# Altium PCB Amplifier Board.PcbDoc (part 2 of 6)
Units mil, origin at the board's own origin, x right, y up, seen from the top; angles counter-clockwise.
Board outline 6000 x 2640 mil, 6 copper layers (Top Layer, GND, VCC, BASES, GND (Plane3), Bottom Layer), stack 63.9 mil thick; 884 components, 484 nets, 2029 pads, 464 vias.
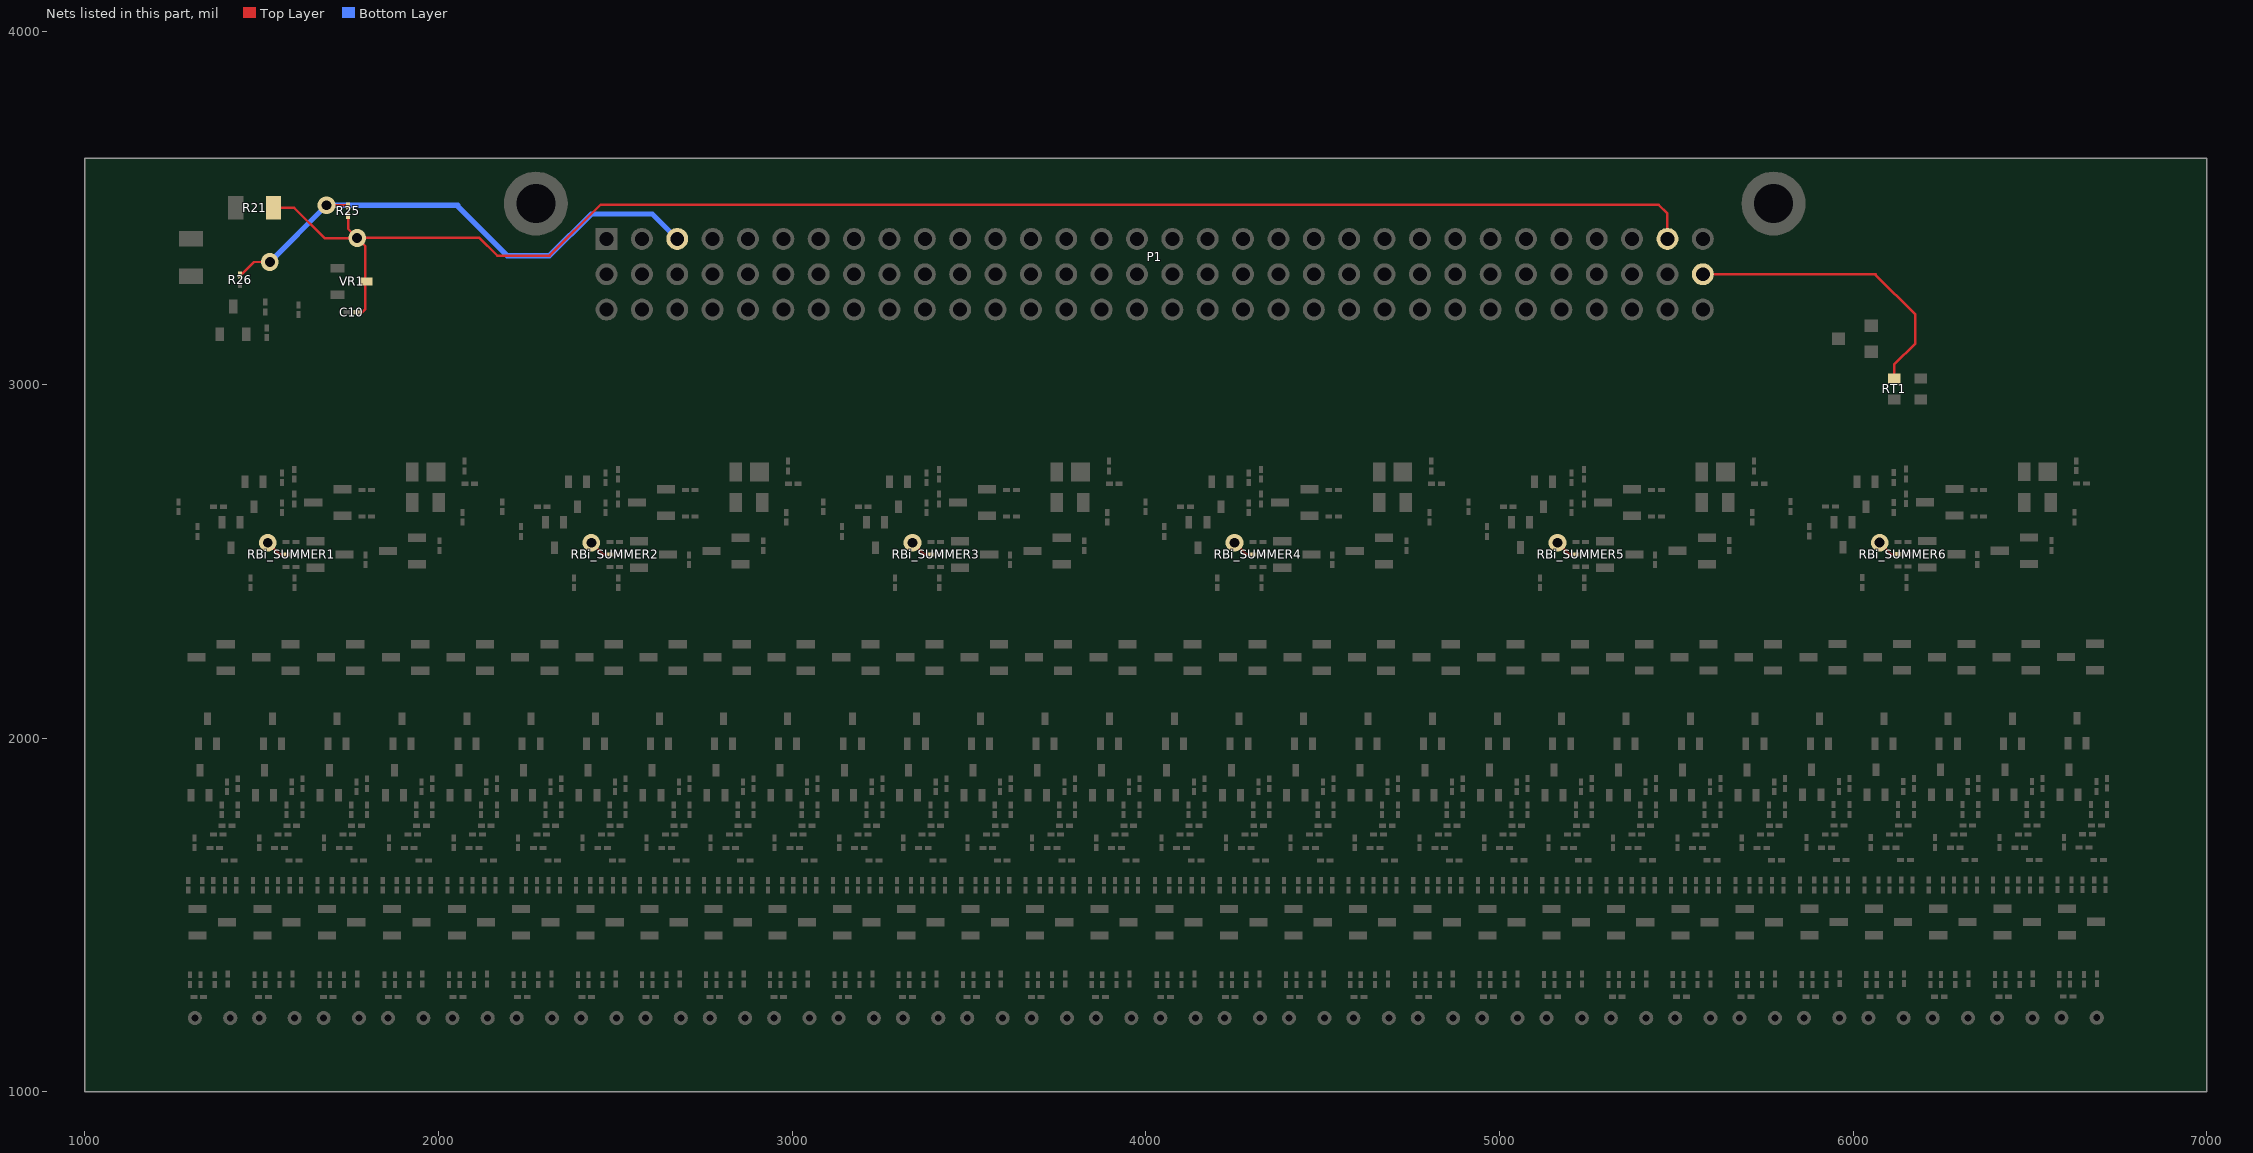
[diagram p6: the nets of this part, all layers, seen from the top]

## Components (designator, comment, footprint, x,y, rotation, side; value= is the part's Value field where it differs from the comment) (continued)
R1_AMP13 "Res2" RESC0603L 3513,1317.78 r90 top (schematic designator R1)
R1_AMP14 "Res2" RESC0603L 3695,1317.78 r90 top (schematic designator R1)
R1_AMP15 "Res2" RESC0603L 3877,1317.78 r90 top (schematic designator R1)
R1_AMP16 "Res2" RESC0603L 4061,1317.78 r90 top (schematic designator R1)
R1_AMP17 "Res2" RESC0603L 4244,1317.78 r90 top (schematic designator R1)
R1_AMP18 "Res2" RESC0603L 4426,1317.78 r90 top (schematic designator R1)
R1_AMP19 "Res2" RESC0603L 4608,1317.78 r90 top (schematic designator R1)
R1_AMP20 "Res2" RESC0603L 4791,1317.78 r90 top (schematic designator R1)
R1_AMP21 "Res2" RESC0603L 4974,1317.88 r90 top (schematic designator R1)
R1_AMP22 "Res2" RESC0603L 5156,1317.88 r90 top (schematic designator R1)
R1_AMP23 "Res2" RESC0603L 5338,1317.88 r90 top (schematic designator R1)
R1_AMP24 "Res2" RESC0603L 5520,1317.88 r90 top (schematic designator R1)
R1_AMP25 "Res2" RESC0603L 5702,1317.88 r90 top (schematic designator R1)
R1_AMP26 "Res2" RESC0603L 5885,1318.35 r90 top (schematic designator R1)
R1_AMP27 "Res2" RESC0603L 6067,1318.35 r90 top (schematic designator R1)
R1_AMP28 "Res2" RESC0603L 6249,1318.35 r90 top (schematic designator R1)
R1_AMP29 "Res2" RESC0603L 6431,1318.35 r90 top (schematic designator R1)
R1_AMP30 "Res2" RESC0603L 6613,1318.78 r90 top (schematic designator R1)
R2_AMP1 "Res2" RESC0603L 1367,1690 r0 top (schematic designator R2)
R2_AMP2 "Res2" RESC0603L 1550,1690 r0 top (schematic designator R2)
R2_AMP3 "Res2" RESC0603L 1733,1690 r0 top (schematic designator R2)
R2_AMP4 "Res2" RESC0603L 1917,1690 r0 top (schematic designator R2)
R2_AMP5 "Res2" RESC0603L 2100,1690 r0 top (schematic designator R2)
R2_AMP6 "Res2" RESC0603L 2282,1690 r0 top (schematic designator R2)
R2_AMP7 "Res2" RESC0603L 2464,1690 r0 top (schematic designator R2)
R2_AMP8 "Res2" RESC0603L 2645,1690 r0 top (schematic designator R2)
R2_AMP9 "Res2" RESC0603L 2826,1690 r0 top (schematic designator R2)
R2_AMP10 "Res2" RESC0603L 3007,1690 r0 top (schematic designator R2)
R2_AMP11 "Res2" RESC0603L 3190,1690 r0 top (schematic designator R2)
R2_AMP12 "Res2" RESC0603L 3371,1690 r0 top (schematic designator R2)
R2_AMP13 "Res2" RESC0603L 3553,1690 r0 top (schematic designator R2)
R2_AMP14 "Res2" RESC0603L 3735,1690 r0 top (schematic designator R2)
R2_AMP15 "Res2" RESC0603L 3917,1690 r0 top (schematic designator R2)
R2_AMP16 "Res2" RESC0603L 4101,1690 r0 top (schematic designator R2)
R2_AMP17 "Res2" RESC0603L 4284,1690 r0 top (schematic designator R2)
R2_AMP18 "Res2" RESC0603L 4466,1690 r0 top (schematic designator R2)
R2_AMP19 "Res2" RESC0603L 4648,1690 r0 top (schematic designator R2)
R2_AMP20 "Res2" RESC0603L 4831,1690 r0 top (schematic designator R2)
R2_AMP21 "Res2" RESC0603L 5014,1690.1 r0 top (schematic designator R2)
R2_AMP22 "Res2" RESC0603L 5196,1690.1 r0 top (schematic designator R2)
R2_AMP23 "Res2" RESC0603L 5378,1690.1 r0 top (schematic designator R2)
R2_AMP24 "Res2" RESC0603L 5560,1690.1 r0 top (schematic designator R2)
R2_AMP25 "Res2" RESC0603L 5742,1690.1 r0 top (schematic designator R2)
R2_AMP26 "Res2" RESC0603L 5925,1690.57 r0 top (schematic designator R2)
R2_AMP27 "Res2" RESC0603L 6107,1690.57 r0 top (schematic designator R2)
R2_AMP28 "Res2" RESC0603L 6289,1690.57 r0 top (schematic designator R2)
R2_AMP29 "Res2" RESC0603L 6471,1690.57 r0 top (schematic designator R2)
R2_AMP30 "Res2" RESC0603L 6653,1691 r0 top (schematic designator R2)
R3_AMP1 "Res2" RESC0603L 1310,1705 r90 top (schematic designator R3)
R3_AMP2 "Res2" RESC0603L 1493,1705 r90 top (schematic designator R3)
R3_AMP3 "Res2" RESC0603L 1676,1705 r90 top (schematic designator R3)
R3_AMP4 "Res2" RESC0603L 1860,1705 r90 top (schematic designator R3)
R3_AMP5 "Res2" RESC0603L 2043,1705 r90 top (schematic designator R3)
R3_AMP6 "Res2" RESC0603L 2225,1705 r90 top (schematic designator R3)
R3_AMP7 "Res2" RESC0603L 2407,1705 r90 top (schematic designator R3)
R3_AMP8 "Res2" RESC0603L 2588,1705 r90 top (schematic designator R3)
R3_AMP9 "Res2" RESC0603L 2769,1705 r90 top (schematic designator R3)
R3_AMP10 "Res2" RESC0603L 2950,1705 r90 top (schematic designator R3)
R3_AMP11 "Res2" RESC0603L 3133,1705 r90 top (schematic designator R3)
R3_AMP12 "Res2" RESC0603L 3314,1705 r90 top (schematic designator R3)
R3_AMP13 "Res2" RESC0603L 3496,1705 r90 top (schematic designator R3)
R3_AMP14 "Res2" RESC0603L 3678,1705 r90 top (schematic designator R3)
R3_AMP15 "Res2" RESC0603L 3860,1705 r90 top (schematic designator R3)
R3_AMP16 "Res2" RESC0603L 4044,1705 r90 top (schematic designator R3)
R3_AMP17 "Res2" RESC0603L 4227,1705 r90 top (schematic designator R3)
R3_AMP18 "Res2" RESC0603L 4409,1705 r90 top (schematic designator R3)
R3_AMP19 "Res2" RESC0603L 4591,1705 r90 top (schematic designator R3)
R3_AMP20 "Res2" RESC0603L 4774,1705 r90 top (schematic designator R3)
R3_AMP21 "Res2" RESC0603L 4957,1705.1 r90 top (schematic designator R3)
R3_AMP22 "Res2" RESC0603L 5139,1705.1 r90 top (schematic designator R3)
R3_AMP23 "Res2" RESC0603L 5321,1705.1 r90 top (schematic designator R3)
R3_AMP24 "Res2" RESC0603L 5503,1705.1 r90 top (schematic designator R3)
R3_AMP25 "Res2" RESC0603L 5685,1705.1 r90 top (schematic designator R3)
R3_AMP26 "Res2" RESC0603L 5868,1705.57 r90 top (schematic designator R3)
R3_AMP27 "Res2" RESC0603L 6050,1705.57 r90 top (schematic designator R3)
R3_AMP28 "Res2" RESC0603L 6232,1705.57 r90 top (schematic designator R3)
R3_AMP29 "Res2" RESC0603L 6414,1705.57 r90 top (schematic designator R3)
R3_AMP30 "Res2" RESC0603L 6596,1706 r90 top (schematic designator R3)
R4_AMP1 "Res2" RESC0603L 1377,1728 r0 top (schematic designator R4)
R4_AMP2 "Res2" RESC0603L 1560,1728 r0 top (schematic designator R4)
R4_AMP3 "Res2" RESC0603L 1743,1728 r0 top (schematic designator R4)
R4_AMP4 "Res2" RESC0603L 1927,1728 r0 top (schematic designator R4)
R4_AMP5 "Res2" RESC0603L 2110,1728 r0 top (schematic designator R4)
R4_AMP6 "Res2" RESC0603L 2292,1728 r0 top (schematic designator R4)
R4_AMP7 "Res2" RESC0603L 2474,1728 r0 top (schematic designator R4)
R4_AMP8 "Res2" RESC0603L 2655,1728 r0 top (schematic designator R4)
R4_AMP9 "Res2" RESC0603L 2836,1728 r0 top (schematic designator R4)
R4_AMP10 "Res2" RESC0603L 3017,1728 r0 top (schematic designator R4)
R4_AMP11 "Res2" RESC0603L 3200,1728 r0 top (schematic designator R4)
R4_AMP12 "Res2" RESC0603L 3381,1728 r0 top (schematic designator R4)
R4_AMP13 "Res2" RESC0603L 3563,1728 r0 top (schematic designator R4)
R4_AMP14 "Res2" RESC0603L 3745,1728 r0 top (schematic designator R4)
R4_AMP15 "Res2" RESC0603L 3927,1728 r0 top (schematic designator R4)
R4_AMP16 "Res2" RESC0603L 4111,1728 r0 top (schematic designator R4)
R4_AMP17 "Res2" RESC0603L 4294,1728 r0 top (schematic designator R4)
R4_AMP18 "Res2" RESC0603L 4476,1728 r0 top (schematic designator R4)
R4_AMP19 "Res2" RESC0603L 4658,1728 r0 top (schematic designator R4)
R4_AMP20 "Res2" RESC0603L 4841,1728 r0 top (schematic designator R4)
R4_AMP21 "Res2" RESC0603L 5024,1728.1 r0 top (schematic designator R4)
R4_AMP22 "Res2" RESC0603L 5206,1728.1 r0 top (schematic designator R4)
R4_AMP23 "Res2" RESC0603L 5388,1728.1 r0 top (schematic designator R4)
R4_AMP24 "Res2" RESC0603L 5570,1728.1 r0 top (schematic designator R4)
R4_AMP25 "Res2" RESC0603L 5752,1728.1 r0 top (schematic designator R4)
R4_AMP26 "Res2" RESC0603L 5935,1728.57 r0 top (schematic designator R4)
R4_AMP27 "Res2" RESC0603L 6117,1728.57 r0 top (schematic designator R4)
R4_AMP28 "Res2" RESC0603L 6299,1728.57 r0 top (schematic designator R4)
R4_AMP29 "Res2" RESC0603L 6481,1728.57 r0 top (schematic designator R4)
R4_AMP30 "Res2" RESC0603L 6663,1729 r0 top (schematic designator R4)
R5_AMP1 "Res2" RESC0603L 1402,1753 r0 top (schematic designator R5)
R5_AMP2 "Res2" RESC0603L 1585,1753 r0 top (schematic designator R5)
R5_AMP3 "Res2" RESC0603L 1768,1753 r0 top (schematic designator R5)
R5_AMP4 "Res2" RESC0603L 1952,1753 r0 top (schematic designator R5)
R5_AMP5 "Res2" RESC0603L 2135,1753 r0 top (schematic designator R5)
R5_AMP6 "Res2" RESC0603L 2317,1753 r0 top (schematic designator R5)
R5_AMP7 "Res2" RESC0603L 2499,1753 r0 top (schematic designator R5)
R5_AMP8 "Res2" RESC0603L 2680,1753 r0 top (schematic designator R5)
R5_AMP9 "Res2" RESC0603L 2861,1753 r0 top (schematic designator R5)
R5_AMP10 "Res2" RESC0603L 3042,1753 r0 top (schematic designator R5)
R5_AMP11 "Res2" RESC0603L 3225,1753 r0 top (schematic designator R5)
R5_AMP12 "Res2" RESC0603L 3406,1753 r0 top (schematic designator R5)
R5_AMP13 "Res2" RESC0603L 3588,1753 r0 top (schematic designator R5)
R5_AMP14 "Res2" RESC0603L 3770,1753 r0 top (schematic designator R5)
R5_AMP15 "Res2" RESC0603L 3952,1753 r0 top (schematic designator R5)
R5_AMP16 "Res2" RESC0603L 4136,1753 r0 top (schematic designator R5)
R5_AMP17 "Res2" RESC0603L 4319,1753 r0 top (schematic designator R5)
R5_AMP18 "Res2" RESC0603L 4501,1753 r0 top (schematic designator R5)
R5_AMP19 "Res2" RESC0603L 4683,1753 r0 top (schematic designator R5)
R5_AMP20 "Res2" RESC0603L 4866,1753 r0 top (schematic designator R5)
R5_AMP21 "Res2" RESC0603L 5049,1753.1 r0 top (schematic designator R5)
R5_AMP22 "Res2" RESC0603L 5231,1753.1 r0 top (schematic designator R5)
R5_AMP23 "Res2" RESC0603L 5413,1753.1 r0 top (schematic designator R5)
R5_AMP24 "Res2" RESC0603L 5595,1753.1 r0 top (schematic designator R5)
R5_AMP25 "Res2" RESC0603L 5777,1753.1 r0 top (schematic designator R5)
R5_AMP26 "Res2" RESC0603L 5960,1753.57 r0 top (schematic designator R5)
R5_AMP27 "Res2" RESC0603L 6142,1753.57 r0 top (schematic designator R5)
R5_AMP28 "Res2" RESC0603L 6324,1753.57 r0 top (schematic designator R5)
R5_AMP29 "Res2" RESC0603L 6506,1753.57 r0 top (schematic designator R5)
R5_AMP30 "Res2" RESC0603L 6688,1754 r0 top (schematic designator R5)
R6_AMP1 "Res2" RESC0603L 1396,1584.78 r90 top (schematic designator R6)
R6_AMP2 "Res2" RESC0603L 1579,1584.78 r90 top (schematic designator R6)
R6_AMP3 "Res2" RESC0603L 1762,1584.78 r90 top (schematic designator R6)
R6_AMP4 "Res2" RESC0603L 1946,1584.78 r90 top (schematic designator R6)
R6_AMP5 "Res2" RESC0603L 2129,1584.78 r90 top (schematic designator R6)
R6_AMP6 "Res2" RESC0603L 2311,1584.78 r90 top (schematic designator R6)
R6_AMP7 "Res2" RESC0603L 2493,1584.78 r90 top (schematic designator R6)
R6_AMP8 "Res2" RESC0603L 2674,1584.78 r90 top (schematic designator R6)
R6_AMP9 "Res2" RESC0603L 2855,1584.78 r90 top (schematic designator R6)
R6_AMP10 "Res2" RESC0603L 3036,1584.78 r90 top (schematic designator R6)
R6_AMP11 "Res2" RESC0603L 3219,1584.78 r90 top (schematic designator R6)
R6_AMP12 "Res2" RESC0603L 3400,1584.78 r90 top (schematic designator R6)
R6_AMP13 "Res2" RESC0603L 3582,1584.78 r90 top (schematic designator R6)
R6_AMP14 "Res2" RESC0603L 3764,1584.78 r90 top (schematic designator R6)
R6_AMP15 "Res2" RESC0603L 3946,1584.78 r90 top (schematic designator R6)
R6_AMP16 "Res2" RESC0603L 4130,1584.78 r90 top (schematic designator R6)
R6_AMP17 "Res2" RESC0603L 4313,1584.78 r90 top (schematic designator R6)
R6_AMP18 "Res2" RESC0603L 4495,1584.78 r90 top (schematic designator R6)
R6_AMP19 "Res2" RESC0603L 4677,1584.78 r90 top (schematic designator R6)
R6_AMP20 "Res2" RESC0603L 4860,1584.78 r90 top (schematic designator R6)
R6_AMP21 "Res2" RESC0603L 5043,1584.88 r90 top (schematic designator R6)
R6_AMP22 "Res2" RESC0603L 5225,1584.88 r90 top (schematic designator R6)
R6_AMP23 "Res2" RESC0603L 5407,1584.88 r90 top (schematic designator R6)
R6_AMP24 "Res2" RESC0603L 5589,1584.88 r90 top (schematic designator R6)
R6_AMP25 "Res2" RESC0603L 5771,1584.88 r90 top (schematic designator R6)
R6_AMP26 "Res2" RESC0603L 5954,1585.35 r90 top (schematic designator R6)
R6_AMP27 "Res2" RESC0603L 6136,1585.35 r90 top (schematic designator R6)
R6_AMP28 "Res2" RESC0603L 6318,1585.35 r90 top (schematic designator R6)
R6_AMP29 "Res2" RESC0603L 6500,1585.35 r90 top (schematic designator R6)
R6_AMP30 "Res2" RESC0603L 6682,1585.78 r90 top (schematic designator R6)
R7_AMP1 "Res2" RESC0603L 1432,1798 r270 top (schematic designator R7)
R7_AMP2 "Res2" RESC0603L 1615,1798 r270 top (schematic designator R7)
R7_AMP3 "Res2" RESC0603L 1798,1798 r270 top (schematic designator R7)
R7_AMP4 "Res2" RESC0603L 1982,1798 r270 top (schematic designator R7)
R7_AMP5 "Res2" RESC0603L 2165,1798 r270 top (schematic designator R7)
R7_AMP6 "Res2" RESC0603L 2347,1798 r270 top (schematic designator R7)
R7_AMP7 "Res2" RESC0603L 2529,1798 r270 top (schematic designator R7)
R7_AMP8 "Res2" RESC0603L 2710,1798 r270 top (schematic designator R7)
R7_AMP9 "Res2" RESC0603L 2891,1798 r270 top (schematic designator R7)
R7_AMP10 "Res2" RESC0603L 3072,1798 r270 top (schematic designator R7)
R7_AMP11 "Res2" RESC0603L 3255,1798 r270 top (schematic designator R7)
R7_AMP12 "Res2" RESC0603L 3436,1798 r270 top (schematic designator R7)
R7_AMP13 "Res2" RESC0603L 3618,1798 r270 top (schematic designator R7)
R7_AMP14 "Res2" RESC0603L 3800,1798 r270 top (schematic designator R7)
R7_AMP15 "Res2" RESC0603L 3982,1798 r270 top (schematic designator R7)
R7_AMP16 "Res2" RESC0603L 4166,1798 r270 top (schematic designator R7)
R7_AMP17 "Res2" RESC0603L 4349,1798 r270 top (schematic designator R7)
R7_AMP18 "Res2" RESC0603L 4531,1798 r270 top (schematic designator R7)
R7_AMP19 "Res2" RESC0603L 4713,1798 r270 top (schematic designator R7)
R7_AMP20 "Res2" RESC0603L 4896,1798 r270 top (schematic designator R7)
R7_AMP21 "Res2" RESC0603L 5079,1798.1 r270 top (schematic designator R7)
R7_AMP22 "Res2" RESC0603L 5261,1798.1 r270 top (schematic designator R7)
R7_AMP23 "Res2" RESC0603L 5443,1798.1 r270 top (schematic designator R7)
R7_AMP24 "Res2" RESC0603L 5625,1798.1 r270 top (schematic designator R7)
R7_AMP25 "Res2" RESC0603L 5807,1798.1 r270 top (schematic designator R7)
R7_AMP26 "Res2" RESC0603L 5990,1798.57 r270 top (schematic designator R7)
R7_AMP27 "Res2" RESC0603L 6172,1798.57 r270 top (schematic designator R7)
R7_AMP28 "Res2" RESC0603L 6354,1798.57 r270 top (schematic designator R7)
R7_AMP29 "Res2" RESC0603L 6536,1798.57 r270 top (schematic designator R7)
R7_AMP30 "Res2" RESC0603L 6718,1799 r270 top (schematic designator R7)
R8_AMP1 "Res2" RESC0603L 1402,1863 r270 top (schematic designator R8)
R8_AMP2 "Res2" RESC0603L 1585,1863 r270 top (schematic designator R8)
R8_AMP3 "Res2" RESC0603L 1768,1863 r270 top (schematic designator R8)
R8_AMP4 "Res2" RESC0603L 1952,1863 r270 top (schematic designator R8)
R8_AMP5 "Res2" RESC0603L 2135,1863 r270 top (schematic designator R8)
R8_AMP6 "Res2" RESC0603L 2317,1863 r270 top (schematic designator R8)
R8_AMP7 "Res2" RESC0603L 2499,1863 r270 top (schematic designator R8)
R8_AMP8 "Res2" RESC0603L 2680,1863 r270 top (schematic designator R8)
R8_AMP9 "Res2" RESC0603L 2861,1863 r270 top (schematic designator R8)
R8_AMP10 "Res2" RESC0603L 3042,1863 r270 top (schematic designator R8)
R8_AMP11 "Res2" RESC0603L 3225,1863 r270 top (schematic designator R8)
R8_AMP12 "Res2" RESC0603L 3406,1863 r270 top (schematic designator R8)
R8_AMP13 "Res2" RESC0603L 3588,1863 r270 top (schematic designator R8)
R8_AMP14 "Res2" RESC0603L 3770,1863 r270 top (schematic designator R8)
R8_AMP15 "Res2" RESC0603L 3952,1863 r270 top (schematic designator R8)
R8_AMP16 "Res2" RESC0603L 4136,1863 r270 top (schematic designator R8)
R8_AMP17 "Res2" RESC0603L 4319,1863 r270 top (schematic designator R8)
R8_AMP18 "Res2" RESC0603L 4501,1863 r270 top (schematic designator R8)
R8_AMP19 "Res2" RESC0603L 4683,1863 r270 top (schematic designator R8)
R8_AMP20 "Res2" RESC0603L 4866,1863 r270 top (schematic designator R8)
R8_AMP21 "Res2" RESC0603L 5049,1863.1 r270 top (schematic designator R8)
R8_AMP22 "Res2" RESC0603L 5231,1863.1 r270 top (schematic designator R8)
R8_AMP23 "Res2" RESC0603L 5413,1863.1 r270 top (schematic designator R8)
R8_AMP24 "Res2" RESC0603L 5595,1863.1 r270 top (schematic designator R8)
R8_AMP25 "Res2" RESC0603L 5777,1863.1 r270 top (schematic designator R8)
R8_AMP26 "Res2" RESC0603L 5960,1863.57 r270 top (schematic designator R8)
R8_AMP27 "Res2" RESC0603L 6142,1863.57 r270 top (schematic designator R8)
R8_AMP28 "Res2" RESC0603L 6324,1863.57 r270 top (schematic designator R8)
R8_AMP29 "Res2" RESC0603L 6506,1863.57 r270 top (schematic designator R8)
R8_AMP30 "Res2" RESC0603L 6688,1864 r270 top (schematic designator R8)
R9_SUMMER1 "Res2" RESC0603L 1468,2440 r270 top (schematic designator R9)
R9_SUMMER2 "Res2" RESC0603L 2383,2440 r270 top (schematic designator R9)
R9_SUMMER3 "Res2" RESC0603L 3291,2440 r270 top (schematic designator R9)
R9_SUMMER4 "Res2" RESC0603L 4202,2440 r270 top (schematic designator R9)
R9_SUMMER5 "Res2" RESC0603L 5115,2440.1 r270 top (schematic designator R9)
R9_SUMMER6 "Res2" RESC0603L 6026,2440.57 r270 top (schematic designator R9)
R10_SUMMER1 "Res2" RESC0603L 2068,2625 r270 top (schematic designator R10)
R10_SUMMER2 "Res2" RESC0603L 2983,2625 r270 top (schematic designator R10)
R10_SUMMER3 "Res2" RESC0603L 3891,2625 r270 top (schematic designator R10)
R10_SUMMER4 "Res2" RESC0603L 4802,2625 r270 top (schematic designator R10)
R10_SUMMER5 "Res2" RESC0603L 5715,2625.1 r270 top (schematic designator R10)
R10_SUMMER6 "Res2" RESC0603L 6626,2625.57 r270 top (schematic designator R10)
R11_SUMMER1 "Res2" RESC0603L 1793,2505 r90 top (schematic designator R11)
R11_SUMMER2 "Res2" RESC0603L 2708,2505 r90 top (schematic designator R11)
R11_SUMMER3 "Res2" RESC0603L 3616,2505 r90 top (schematic designator R11)
R11_SUMMER4 "Res2" RESC0603L 4527,2505 r90 top (schematic designator R11)
R11_SUMMER5 "Res2" RESC0603L 5440,2505.1 r90 top (schematic designator R11)
R11_SUMMER6 "Res2" RESC0603L 6351,2505.57 r90 top (schematic designator R11)
R12_SUMMER1 "Res2" RESC0603L 1583,2485 r0 top (schematic designator R12)
R12_SUMMER2 "Res2" RESC0603L 2498,2485 r0 top (schematic designator R12)
R12_SUMMER3 "Res2" RESC0603L 3406,2485 r0 top (schematic designator R12)
R12_SUMMER4 "Res2" RESC0603L 4317,2485 r0 top (schematic designator R12)
R12_SUMMER5 "Res2" RESC0603L 5230,2485.1 r0 top (schematic designator R12)
R12_SUMMER6 "Res2" RESC0603L 6141,2485.57 r0 top (schematic designator R12)
R13_SUMMER1 "Res2" RESC0603L 1592,2747 r90 top (schematic designator R13)
R13_SUMMER2 "Res2" RESC0603L 2507,2747 r90 top (schematic designator R13)
R13_SUMMER3 "Res2" RESC0603L 3415,2747 r90 top (schematic designator R13)
R13_SUMMER4 "Res2" RESC0603L 4326,2747 r90 top (schematic designator R13)
R13_SUMMER5 "Res2" RESC0603L 5239,2747.1 r90 top (schematic designator R13)
R13_SUMMER6 "Res2" RESC0603L 6150,2747.57 r90 top (schematic designator R13)
R14_SUMMER1 "Res2" RESC0603L 1797,2702 r180 top (schematic designator R14)
R14_SUMMER2 "Res2" RESC0603L 2712,2702 r180 top (schematic designator R14)
R14_SUMMER3 "Res2" RESC0603L 3620,2702 r180 top (schematic designator R14)
R14_SUMMER4 "Res2" RESC0603L 4531,2702 r180 top (schematic designator R14)
R14_SUMMER5 "Res2" RESC0603L 5444,2702.1 r180 top (schematic designator R14)
R14_SUMMER6 "Res2" RESC0603L 6355,2702.57 r180 top (schematic designator R14)
R15_SUMMER1 "Res2" RESC0603L 1378,2655 r180 top (schematic designator R15)
R15_SUMMER2 "Res2" RESC0603L 2293,2655 r180 top (schematic designator R15)
R15_SUMMER3 "Res2" RESC0603L 3201,2655 r180 top (schematic designator R15)
R15_SUMMER4 "Res2" RESC0603L 4112,2655 r180 top (schematic designator R15)
R15_SUMMER5 "Res2" RESC0603L 5025,2655.1 r180 top (schematic designator R15)
R15_SUMMER6 "Res2" RESC0603L 5936,2655.57 r180 top (schematic designator R15)
R16_SUMMER1 "Res2" RESC0603L 1318,2585 r90 top (schematic designator R16)
R16_SUMMER2 "Res2" RESC0603L 2233,2585 r90 top (schematic designator R16)
R16_SUMMER3 "Res2" RESC0603L 3141,2585 r90 top (schematic designator R16)
R16_SUMMER4 "Res2" RESC0603L 4052,2585 r90 top (schematic designator R16)
R16_SUMMER5 "Res2" RESC0603L 4965,2585.1 r90 top (schematic designator R16)
R16_SUMMER6 "Res2" RESC0603L 5876,2585.57 r90 top (schematic designator R16)
R17_SUMMER1 "Res2" RESC0603L 1797,2627 r180 top (schematic designator R17)
R17_SUMMER2 "Res2" RESC0603L 2712,2627 r180 top (schematic designator R17)
R17_SUMMER3 "Res2" RESC0603L 3620,2627 r180 top (schematic designator R17)
R17_SUMMER4 "Res2" RESC0603L 4531,2627 r180 top (schematic designator R17)
R17_SUMMER5 "Res2" RESC0603L 5444,2627.1 r180 top (schematic designator R17)
R17_SUMMER6 "Res2" RESC0603L 6355,2627.57 r180 top (schematic designator R17)
R18_AMP1 "Res2" RESC0603L 1404,1319.43 r270 top (schematic designator R18)
R18_AMP2 "Res2" RESC0603L 1587,1319.43 r270 top (schematic designator R18)
R18_AMP3 "Res2" RESC0603L 1770,1319.43 r270 top (schematic designator R18)
R18_AMP4 "Res2" RESC0603L 1954,1319.43 r270 top (schematic designator R18)
R18_AMP5 "Res2" RESC0603L 2137,1319.43 r270 top (schematic designator R18)
R18_AMP6 "Res2" RESC0603L 2319,1319.43 r270 top (schematic designator R18)
R18_AMP7 "Res2" RESC0603L 2501,1319.43 r270 top (schematic designator R18)
R18_AMP8 "Res2" RESC0603L 2682,1319.43 r270 top (schematic designator R18)
R18_AMP9 "Res2" RESC0603L 2863,1319.43 r270 top (schematic designator R18)
R18_AMP10 "Res2" RESC0603L 3044,1319.43 r270 top (schematic designator R18)
R18_AMP11 "Res2" RESC0603L 3227,1319.43 r270 top (schematic designator R18)
R18_AMP12 "Res2" RESC0603L 3408,1319.43 r270 top (schematic designator R18)
R18_AMP13 "Res2" RESC0603L 3590,1319.43 r270 top (schematic designator R18)
R18_AMP14 "Res2" RESC0603L 3772,1319.43 r270 top (schematic designator R18)
R18_AMP15 "Res2" RESC0603L 3954,1319.43 r270 top (schematic designator R18)
R18_AMP16 "Res2" RESC0603L 4138,1319.43 r270 top (schematic designator R18)
R18_AMP17 "Res2" RESC0603L 4321,1319.43 r270 top (schematic designator R18)
R18_AMP18 "Res2" RESC0603L 4503,1319.43 r270 top (schematic designator R18)
R18_AMP19 "Res2" RESC0603L 4685,1319.43 r270 top (schematic designator R18)
R18_AMP20 "Res2" RESC0603L 4868,1319.43 r270 top (schematic designator R18)
R18_AMP21 "Res2" RESC0603L 5051,1319.53 r270 top (schematic designator R18)
R18_AMP22 "Res2" RESC0603L 5233,1319.53 r270 top (schematic designator R18)
R18_AMP23 "Res2" RESC0603L 5415,1319.53 r270 top (schematic designator R18)
R18_AMP24 "Res2" RESC0603L 5597,1319.53 r270 top (schematic designator R18)
R18_AMP25 "Res2" RESC0603L 5779,1319.53 r270 top (schematic designator R18)
R18_AMP26 "Res2" RESC0603L 5962,1320 r270 top (schematic designator R18)
R18_AMP27 "Res2" RESC0603L 6144,1320 r270 top (schematic designator R18)
R18_AMP28 "Res2" RESC0603L 6326,1320 r270 top (schematic designator R18)
R18_AMP29 "Res2" RESC0603L 6508,1320 r270 top (schematic designator R18)
R18_AMP30 "Res2" RESC0603L 6690,1320.43 r270 top (schematic designator R18)
R19_AMP1 "Res2" RESC0603L 1322,1269 r180 top (schematic designator R19)
R19_AMP2 "Res2" RESC0603L 1505,1269 r180 top (schematic designator R19)
R19_AMP3 "Res2" RESC0603L 1688,1269 r180 top (schematic designator R19)
R19_AMP4 "Res2" RESC0603L 1872,1269 r180 top (schematic designator R19)
R19_AMP5 "Res2" RESC0603L 2055,1269 r180 top (schematic designator R19)
R19_AMP6 "Res2" RESC0603L 2237,1269 r180 top (schematic designator R19)
R19_AMP7 "Res2" RESC0603L 2419,1269 r180 top (schematic designator R19)
R19_AMP8 "Res2" RESC0603L 2600,1269 r180 top (schematic designator R19)
R19_AMP9 "Res2" RESC0603L 2781,1269 r180 top (schematic designator R19)
R19_AMP10 "Res2" RESC0603L 2962,1269 r180 top (schematic designator R19)
R19_AMP11 "Res2" RESC0603L 3145,1269 r180 top (schematic designator R19)
R19_AMP12 "Res2" RESC0603L 3326,1269 r180 top (schematic designator R19)
R19_AMP13 "Res2" RESC0603L 3508,1269 r180 top (schematic designator R19)
R19_AMP14 "Res2" RESC0603L 3690,1269 r180 top (schematic designator R19)
R19_AMP15 "Res2" RESC0603L 3872,1269 r180 top (schematic designator R19)
R19_AMP16 "Res2" RESC0603L 4056,1269 r180 top (schematic designator R19)
R19_AMP17 "Res2" RESC0603L 4239,1269 r180 top (schematic designator R19)
R19_AMP18 "Res2" RESC0603L 4421,1269 r180 top (schematic designator R19)
R19_AMP19 "Res2" RESC0603L 4603,1269 r180 top (schematic designator R19)
R19_AMP20 "Res2" RESC0603L 4786,1269 r180 top (schematic designator R19)
R19_AMP21 "Res2" RESC0603L 4969,1269.1 r180 top (schematic designator R19)
R19_AMP22 "Res2" RESC0603L 5151,1269.1 r180 top (schematic designator R19)
R19_AMP23 "Res2" RESC0603L 5333,1269.1 r180 top (schematic designator R19)
R19_AMP24 "Res2" RESC0603L 5515,1269.1 r180 top (schematic designator R19)
R19_AMP25 "Res2" RESC0603L 5697,1269.1 r180 top (schematic designator R19)
R19_AMP26 "Res2" RESC0603L 5880,1269.57 r180 top (schematic designator R19)
R19_AMP27 "Res2" RESC0603L 6062,1269.57 r180 top (schematic designator R19)
R19_AMP28 "Res2" RESC0603L 6244,1269.57 r180 top (schematic designator R19)
R19_AMP29 "Res2" RESC0603L 6426,1269.57 r180 top (schematic designator R19)
R19_AMP30 "Res2" RESC0603L 6608,1270 r180 top (schematic designator R19)
R20_AMP1 "Res2" RESC0603L 1408.22,1655 r180 top (schematic designator R20)
R20_AMP2 "Res2" RESC0603L 1591.22,1655 r180 top (schematic designator R20)
R20_AMP3 "Res2" RESC0603L 1774.22,1655 r180 top (schematic designator R20)
R20_AMP4 "Res2" RESC0603L 1958.22,1655 r180 top (schematic designator R20)
R20_AMP5 "Res2" RESC0603L 2141.22,1655 r180 top (schematic designator R20)
R20_AMP6 "Res2" RESC0603L 2323.22,1655 r180 top (schematic designator R20)
R20_AMP7 "Res2" RESC0603L 2505.22,1655 r180 top (schematic designator R20)
R20_AMP8 "Res2" RESC0603L 2686.22,1655 r180 top (schematic designator R20)
R20_AMP9 "Res2" RESC0603L 2867.22,1655 r180 top (schematic designator R20)
R20_AMP10 "Res2" RESC0603L 3048.22,1655 r180 top (schematic designator R20)
R20_AMP11 "Res2" RESC0603L 3231.22,1655 r180 top (schematic designator R20)
R20_AMP12 "Res2" RESC0603L 3412.22,1655 r180 top (schematic designator R20)
R20_AMP13 "Res2" RESC0603L 3594.22,1655 r180 top (schematic designator R20)
R20_AMP14 "Res2" RESC0603L 3776.22,1655 r180 top (schematic designator R20)
R20_AMP15 "Res2" RESC0603L 3958.22,1655 r180 top (schematic designator R20)
R20_AMP16 "Res2" RESC0603L 4142.22,1655 r180 top (schematic designator R20)
R20_AMP17 "Res2" RESC0603L 4325.22,1655 r180 top (schematic designator R20)
R20_AMP18 "Res2" RESC0603L 4507.22,1655 r180 top (schematic designator R20)
R20_AMP19 "Res2" RESC0603L 4689.22,1655 r180 top (schematic designator R20)
R20_AMP20 "Res2" RESC0603L 4872.22,1655 r180 top (schematic designator R20)
R20_AMP21 "Res2" RESC0603L 5055.22,1655.1 r180 top (schematic designator R20)
R20_AMP22 "Res2" RESC0603L 5237.22,1655.1 r180 top (schematic designator R20)
R20_AMP23 "Res2" RESC0603L 5419.22,1655.1 r180 top (schematic designator R20)
R20_AMP24 "Res2" RESC0603L 5601.22,1655.1 r180 top (schematic designator R20)
R20_AMP25 "Res2" RESC0603L 5783.22,1655.1 r180 top (schematic designator R20)
R20_AMP26 "Res2" RESC0603L 5966.22,1655.57 r180 top (schematic designator R20)
R20_AMP27 "Res2" RESC0603L 6148.22,1655.57 r180 top (schematic designator R20)
R20_AMP28 "Res2" RESC0603L 6330.22,1655.57 r180 top (schematic designator R20)
R20_AMP29 "Res2" RESC0603L 6512.22,1655.57 r180 top (schematic designator R20)
R20_AMP30 "Res2" RESC0603L 6694.22,1656 r180 top (schematic designator R20)
R21 "Res2" RESC3216L 1480,3500 r180 top
R22 "Res2" RESC0603L 1604,3212 r270 top
R23 "Res2" RESC3216L 1300,3360 r270 top
R24 "Res2" RESC0603L 1514,3147 r90 top
R25 "Res2" RESC0603L 1744,3492 r270 top
R26 "Res2" RESC0603L 1439,3297 r270 top
R27 "Res2" RESC1608L 6191,2988 r270 top
RBi_AMP1 "Res2" RESC0603L 1332,1584.78 r270 top (schematic designator RBi)
RBi_AMP2 "Res2" RESC0603L 1515,1584.78 r270 top (schematic designator RBi)
RBi_AMP3 "Res2" RESC0603L 1698,1584.78 r270 top (schematic designator RBi)
RBi_AMP4 "Res2" RESC0603L 1882,1584.78 r270 top (schematic designator RBi)
RBi_AMP5 "Res2" RESC0603L 2065,1584.78 r270 top (schematic designator RBi)
RBi_AMP6 "Res2" RESC0603L 2247,1584.78 r270 top (schematic designator RBi)
RBi_AMP7 "Res2" RESC0603L 2429,1584.78 r270 top (schematic designator RBi)
RBi_AMP8 "Res2" RESC0603L 2610,1584.78 r270 top (schematic designator RBi)
RBi_AMP9 "Res2" RESC0603L 2791,1584.78 r270 top (schematic designator RBi)
RBi_AMP10 "Res2" RESC0603L 2972,1584.78 r270 top (schematic designator RBi)
RBi_AMP11 "Res2" RESC0603L 3155,1584.78 r270 top (schematic designator RBi)
RBi_AMP12 "Res2" RESC0603L 3336,1584.78 r270 top (schematic designator RBi)
RBi_AMP13 "Res2" RESC0603L 3518,1584.78 r270 top (schematic designator RBi)
RBi_AMP14 "Res2" RESC0603L 3700,1584.78 r270 top (schematic designator RBi)
RBi_AMP15 "Res2" RESC0603L 3882,1584.78 r270 top (schematic designator RBi)
RBi_AMP16 "Res2" RESC0603L 4066,1584.78 r270 top (schematic designator RBi)
RBi_AMP17 "Res2" RESC0603L 4249,1584.78 r270 top (schematic designator RBi)
RBi_AMP18 "Res2" RESC0603L 4431,1584.78 r270 top (schematic designator RBi)
RBi_AMP19 "Res2" RESC0603L 4613,1584.78 r270 top (schematic designator RBi)
RBi_AMP20 "Res2" RESC0603L 4796,1584.78 r270 top (schematic designator RBi)
RBi_AMP21 "Res2" RESC0603L 4979,1584.88 r270 top (schematic designator RBi)
RBi_AMP22 "Res2" RESC0603L 5161,1584.88 r270 top (schematic designator RBi)
RBi_AMP23 "Res2" RESC0603L 5343,1584.88 r270 top (schematic designator RBi)
RBi_AMP24 "Res2" RESC0603L 5525,1584.88 r270 top (schematic designator RBi)
RBi_AMP25 "Res2" RESC0603L 5707,1584.88 r270 top (schematic designator RBi)
RBi_AMP26 "Res2" RESC0603L 5890,1585.35 r270 top (schematic designator RBi)
RBi_AMP27 "Res2" RESC0603L 6072,1585.35 r270 top (schematic designator RBi)
RBi_AMP28 "Res2" RESC0603L 6254,1585.35 r270 top (schematic designator RBi)
RBi_AMP29 "Res2" RESC0603L 6436,1585.35 r270 top (schematic designator RBi)
RBi_AMP30 "Res2" RESC0603L 6618,1585.78 r270 top (schematic designator RBi)
RBi_SUMMER1 "Res2" RESC0603L 1583,2520 r0 top (schematic designator RBi)
RBi_SUMMER2 "Res2" RESC0603L 2498,2520 r0 top (schematic designator RBi)
RBi_SUMMER3 "Res2" RESC0603L 3406,2520 r0 top (schematic designator RBi)
RBi_SUMMER4 "Res2" RESC0603L 4317,2520 r0 top (schematic designator RBi)
RBi_SUMMER5 "Res2" RESC0603L 5230,2520.1 r0 top (schematic designator RBi)
RBi_SUMMER6 "Res2" RESC0603L 6141,2520.57 r0 top (schematic designator RBi)
RC_SUMMER1 "Res2" RESC0603L 1557,2652 r90 top (schematic designator RC)
RC_SUMMER2 "Res2" RESC0603L 2472,2652 r90 top (schematic designator RC)
RC_SUMMER3 "Res2" RESC0603L 3380,2652 r90 top (schematic designator RC)
RC_SUMMER4 "Res2" RESC0603L 4291,2652 r90 top (schematic designator RC)
RC_SUMMER5 "Res2" RESC0603L 5204,2652.1 r90 top (schematic designator RC)
RC_SUMMER6 "Res2" RESC0603L 6115,2652.57 r90 top (schematic designator RC)
RD_SUMMER1 "Res2" RESC0603L 1557,2737 r90 top (schematic designator RD)
RD_SUMMER2 "Res2" RESC0603L 2472,2737 r90 top (schematic designator RD)
RD_SUMMER3 "Res2" RESC0603L 3380,2737 r90 top (schematic designator RD)
RD_SUMMER4 "Res2" RESC0603L 4291,2737 r90 top (schematic designator RD)
RD_SUMMER5 "Res2" RESC0603L 5204,2737.1 r90 top (schematic designator RD)
RD_SUMMER6 "Res2" RESC0603L 6115,2737.57 r90 top (schematic designator RD)
RG_SUMMER1 "Res2" RESC0603L 2073,2770 r90 top (schematic designator RG)
RG_SUMMER2 "Res2" RESC0603L 2988,2770 r90 top (schematic designator RG)
RG_SUMMER3 "Res2" RESC0603L 3896,2770 r90 top (schematic designator RG)
RG_SUMMER4 "Res2" RESC0603L 4807,2770 r90 top (schematic designator RG)
RG_SUMMER5 "Res2" RESC0603L 5720,2770.1 r90 top (schematic designator RG)
RG_SUMMER6 "Res2" RESC0603L 6631,2770.57 r90 top (schematic designator RG)
RT1 "Res Thermal" RESC1608L 6116,2988 r90 top
SIPM_AMP1 "Photo Sen" "Photonique SiPM" 1361,1159 r0 top (schematic designator SIPM)
SIPM_AMP2 "Photo Sen" "Photonique SiPM" 1543,1159 r0 top (schematic designator SIPM)
SIPM_AMP3 "Photo Sen" "Photonique SiPM" 1725,1159 r0 top (schematic designator SIPM)
SIPM_AMP4 "Photo Sen" "Photonique SiPM" 1907,1159 r0 top (schematic designator SIPM)
SIPM_AMP5 "Photo Sen" "Photonique SiPM" 2089,1159 r0 top (schematic designator SIPM)
SIPM_AMP6 "Photo Sen" "Photonique SiPM" 2271,1159 r0 top (schematic designator SIPM)
SIPM_AMP7 "Photo Sen" "Photonique SiPM" 2453,1159 r0 top (schematic designator SIPM)
SIPM_AMP8 "Photo Sen" "Photonique SiPM" 2635,1159 r0 top (schematic designator SIPM)
SIPM_AMP9 "Photo Sen" "Photonique SiPM" 2817,1159 r0 top (schematic designator SIPM)
SIPM_AMP10 "Photo Sen" "Photonique SiPM" 2999,1159 r0 top (schematic designator SIPM)
SIPM_AMP11 "Photo Sen" "Photonique SiPM" 3181,1159 r0 top (schematic designator SIPM)
SIPM_AMP12 "Photo Sen" "Photonique SiPM" 3363,1159 r0 top (schematic designator SIPM)
SIPM_AMP13 "Photo Sen" "Photonique SiPM" 3545,1159 r0 top (schematic designator SIPM)
SIPM_AMP14 "Photo Sen" "Photonique SiPM" 3727,1159 r0 top (schematic designator SIPM)
SIPM_AMP15 "Photo Sen" "Photonique SiPM" 3909,1159 r0 top (schematic designator SIPM)
SIPM_AMP16 "Photo Sen" "Photonique SiPM" 4091,1159 r0 top (schematic designator SIPM)
SIPM_AMP17 "Photo Sen" "Photonique SiPM" 4273,1159 r0 top (schematic designator SIPM)
SIPM_AMP18 "Photo Sen" "Photonique SiPM" 4455,1159 r0 top (schematic designator SIPM)
SIPM_AMP19 "Photo Sen" "Photonique SiPM" 4637,1159 r0 top (schematic designator SIPM)
SIPM_AMP20 "Photo Sen" "Photonique SiPM" 4819,1159 r0 top (schematic designator SIPM)
SIPM_AMP21 "Photo Sen" "Photonique SiPM" 5001,1159.1 r0 top (schematic designator SIPM)
SIPM_AMP22 "Photo Sen" "Photonique SiPM" 5183,1159.1 r0 top (schematic designator SIPM)
SIPM_AMP23 "Photo Sen" "Photonique SiPM" 5365,1159.1 r0 top (schematic designator SIPM)
SIPM_AMP24 "Photo Sen" "Photonique SiPM" 5547,1159.1 r0 top (schematic designator SIPM)
SIPM_AMP25 "Photo Sen" "Photonique SiPM" 5729,1159.1 r0 top (schematic designator SIPM)
SIPM_AMP26 "Photo Sen" "Photonique SiPM" 5911,1159.57 r0 top (schematic designator SIPM)
SIPM_AMP27 "Photo Sen" "Photonique SiPM" 6093,1159.57 r0 top (schematic designator SIPM)
SIPM_AMP28 "Photo Sen" "Photonique SiPM" 6275,1159.57 r0 top (schematic designator SIPM)
SIPM_AMP29 "Photo Sen" "Photonique SiPM" 6457,1159.57 r0 top (schematic designator SIPM)
SIPM_AMP30 "Photo Sen" "Photonique SiPM" 6639,1160 r0 top (schematic designator SIPM)
VR1 "Volt Reg" SOT23_L 1754,3292 r0 top
VR2 "Volt Reg" SOT23_L 1419,3182 r90 top

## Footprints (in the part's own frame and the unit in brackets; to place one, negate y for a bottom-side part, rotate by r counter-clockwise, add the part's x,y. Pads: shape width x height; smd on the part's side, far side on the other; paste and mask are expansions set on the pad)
EURO2.54-2H96 [mm] "Connector; DIN 41612, Type C, Thru-Hole; Rows a+b+c, 96 Position; Right Angle"
  round 4.6 hole 2.8: 33(-44.45,-10.1) 34(44.45,-10.1)
  rect 1.575x1.575 hole 1: A1(-39.37,-12.64)
  round 1.575 hole 1: A2(-36.83,-12.64) A3(-34.29,-12.64) A4(-31.75,-12.64) A5(-29.21,-12.64) A6(-26.67,-12.64) A7(-24.13,-12.64) A8(-21.59,-12.64) A9(-19.05,-12.64) A10(-16.51,-12.64) A11(-13.97,-12.64) A12(-11.43,-12.64) A13(-8.89,-12.64) A14(-6.35,-12.64) A15(-3.81,-12.64) A16(-1.27,-12.64) A17(1.27,-12.64) A18(3.81,-12.64) A19(6.35,-12.64) A20(8.89,-12.64) A21(11.43,-12.64) A22(13.97,-12.64) A23(16.51,-12.64) A24(19.05,-12.64) A25(21.59,-12.64) A26(24.13,-12.64) A27(26.67,-12.64) A28(29.21,-12.64) A29(31.75,-12.64) A30(34.29,-12.64) A31(36.83,-12.64) A32(39.37,-12.64) B1(-39.37,-15.18) B2(-36.83,-15.18) B3(-34.29,-15.18) B4(-31.75,-15.18) B5(-29.21,-15.18) B6(-26.67,-15.18) B7(-24.13,-15.18) B8(-21.59,-15.18) B9(-19.05,-15.18) B10(-16.51,-15.18) B11(-13.97,-15.18) B12(-11.43,-15.18) B13(-8.89,-15.18) B14(-6.35,-15.18) B15(-3.81,-15.18) B16(-1.27,-15.18) B17(1.27,-15.18) B18(3.81,-15.18) B19(6.35,-15.18) B20(8.89,-15.18) B21(11.43,-15.18) B22(13.97,-15.18) B23(16.51,-15.18) B24(19.05,-15.18) B25(21.59,-15.18) B26(24.13,-15.18) B27(26.67,-15.18) B28(29.21,-15.18) B29(31.75,-15.18) B30(34.29,-15.18) B31(36.83,-15.18) B32(39.37,-15.18) C1(-39.37,-17.72) C2(-36.83,-17.72) C3(-34.29,-17.72) C4(-31.75,-17.72) C5(-29.21,-17.72) C6(-26.67,-17.72) C7(-24.13,-17.72) C8(-21.59,-17.72) C9(-19.05,-17.72) C10(-16.51,-17.72) C11(-13.97,-17.72) C12(-11.43,-17.72) C13(-8.89,-17.72) C14(-6.35,-17.72) C15(-3.81,-17.72) C16(-1.27,-17.72) C17(1.27,-17.72) C18(3.81,-17.72) C19(6.35,-17.72) C20(8.89,-17.72) C21(11.43,-17.72) C22(13.97,-17.72) C23(16.51,-17.72) C24(19.05,-17.72) C25(21.59,-17.72) C26(24.13,-17.72) C27(26.67,-17.72) C28(29.21,-17.72) C29(31.75,-17.72) C30(34.29,-17.72) C31(36.83,-17.72) C32(39.37,-17.72)
  silkscreen extent -47,-13.14 47,0
"Photonique SiPM" [mil]
  round 40 hole 19.7: 1(-50,50) 2(50,50)
RESC0603L [mm] "Chip Resistor, Body 0.6x0.3mm, IPC High Density"
  rect 0.5x0.3 smd: 1(-0.35,0) 2(0.35,0)
  body extent -0.32,-0.17 0.32,0.17, height 0.3
RESC1608L [mm] "Chip Resistor, Body 1.6x0.8mm, IPC High Density"
  rect 0.7x0.9 smd: 1(-0.75,0) 2(0.75,0)
  silkscreen extent -0.2,-0.35 0.2,0.35, body extent -0.85,-0.48 0.85,0.48, height 0.6
RESC3216L [mm] "Chip Resistor, Body 3.2x1.6mm, IPC High Density"
  rect 1.1x1.7 smd: 1(-1.35,0) 2(1.35,0)
  silkscreen extent -0.4,-0.75 0.4,0.75, body extent -1.68,-0.87 1.68,0.87, height 0.71
SOT23 [mm] "SOT-23; 3 Leads; Body 3.1 x 2.5 mm, inc. leads (LxW max), Alternate Lead Configuration"
  rect 0.9x0.95 smd: 1(-0.95,-1.175) 2(0,1.175) 3(0.95,-1.175)
  silkscreen extent -1.3,-0.3 1.3,2.32
SOT23_L [mm] "SOT23, 3-Leads, Body 2.9x1.3mm, Pitch 0.95mm, Lead Span 2.3mm, IPC High Density"
  rect 1x0.6 smd: 1(-1,0.95) 2(-1,-0.95) 3(1,0)
  silkscreen extent -1.12,-1.5 0.7,1.92, body extent -0.7,-1.5 0.7,1.5, height 1.1
SOT23_N [mm] "SOT23, 3-Leads, Body 2.9x1.3mm, Pitch 0.95mm, Lead Span 2.3mm, IPC Medium Density"
  rect 1.3x0.6 smd: 1(-1.05,0.95) 2(-1.05,-0.95) 3(1.05,0)
  silkscreen extent -1.17,-1.5 0.7,1.92, body extent -0.7,-1.5 0.7,1.5, height 1.1
SOT323_L [mm] "SOT323, 3-Leads, Body 2.0x1.3mm, Pitch 0.65mm, Lead Span 2.1mm, IPC High Density"
  rect 0.9x0.5 smd: 1(-0.9,0.65) 2(-0.9,-0.65) 3(0.9,0)
  silkscreen extent -1.02,-1.1 0.7,1.57, body extent -0.7,-1.1 0.7,1.1, height 1.1
SOT-143 [mm] "SOT-143; 4 Leads; Body 3 x 2.6 mm, inc. leads (LxW max)"
  rect 1.35x1.35 smd: 1(-0.75,-1.1)
  rect 0.9x1.35 smd: 2(0.95,-1.1) 3(0.95,1.1) 4(-0.95,1.1)
  silkscreen extent -1.88,-2.22 1.75,0.7

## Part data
C1_AMP1 C1_AMP2 C1_AMP3 C1_AMP4 C1_AMP5 C1_AMP6 C1_AMP7 C1_AMP8 C1_AMP9 C1_AMP10 C1_AMP11 C1_AMP12 C1_AMP13 C1_AMP14 C1_AMP15 C1_AMP16 C1_AMP17 C1_AMP18 C1_AMP19 C1_AMP20 C1_AMP21 C1_AMP22 C1_AMP23 C1_AMP24 C1_AMP25 C1_AMP26 C1_AMP27 C1_AMP28 C1_AMP29 C1_AMP30 C2_AMP1 C2_AMP2 C2_AMP3 C2_AMP4 C2_AMP5 C2_AMP6 C2_AMP7 C2_AMP8 C2_AMP9 C2_AMP10 C2_AMP11 C2_AMP12 C2_AMP13 C2_AMP14 C2_AMP15 C2_AMP16 C2_AMP17 C2_AMP18 C2_AMP19 C2_AMP20 C2_AMP21 C2_AMP22 C2_AMP23 C2_AMP24 C2_AMP25 C2_AMP26 C2_AMP27 C2_AMP28 C2_AMP29 C2_AMP30 C3_AMP1 C3_AMP2 C3_AMP3 C3_AMP4 C3_AMP5 C3_AMP6 C3_AMP7 C3_AMP8 C3_AMP9 C3_AMP10 C3_AMP11 C3_AMP12 C3_AMP13 C3_AMP14 C3_AMP15 C3_AMP16 C3_AMP17 C3_AMP18 C3_AMP19 C3_AMP20 C3_AMP21 C3_AMP22 C3_AMP23 C3_AMP24 C3_AMP25 C3_AMP26 C3_AMP27 C3_AMP28 C3_AMP29 C3_AMP30 C4_AMP1 C4_AMP2 C4_AMP3 C4_AMP4 C4_AMP5 C4_AMP6 C4_AMP7 C4_AMP8 C4_AMP9 C4_AMP10 C4_AMP11 C4_AMP12 C4_AMP13 C4_AMP14 C4_AMP15 C4_AMP16 C4_AMP17 C4_AMP18 C4_AMP19 C4_AMP20 C4_AMP21 C4_AMP22 C4_AMP23 C4_AMP24 C4_AMP25 C4_AMP26 C4_AMP27 C4_AMP28 C4_AMP29 C4_AMP30 C5_AMP1 C5_AMP2 C5_AMP3 C5_AMP4 C5_AMP5 C5_AMP6 C5_AMP7 C5_AMP8 C5_AMP9 C5_AMP10 C5_AMP11 C5_AMP12 C5_AMP13 C5_AMP14 C5_AMP15 C5_AMP16 C5_AMP17 C5_AMP18 C5_AMP19 C5_AMP20 C5_AMP21 C5_AMP22 C5_AMP23 C5_AMP24 C5_AMP25 C5_AMP26 C5_AMP27 C5_AMP28 C5_AMP29 C5_AMP30 C5_SUMMER1 C5_SUMMER2 C5_SUMMER3 C5_SUMMER4 C5_SUMMER5 C5_SUMMER6 C6_AMP1 C6_AMP2 C6_AMP3 C6_AMP4 C6_AMP5 C6_AMP6 C6_AMP7 C6_AMP8 C6_AMP9 C6_AMP10 C6_AMP11 C6_AMP12 C6_AMP13 C6_AMP14 C6_AMP15 C6_AMP16 C6_AMP17 C6_AMP18 C6_AMP19 C6_AMP20 C6_AMP21 C6_AMP22 C6_AMP23 C6_AMP24 C6_AMP25 C6_AMP26 C6_AMP27 C6_AMP28 C6_AMP29 C6_AMP30 C7_SUMMER1 C7_SUMMER2 C7_SUMMER3 C7_SUMMER4 C7_SUMMER5 C7_SUMMER6 C8_SUMMER1 C8_SUMMER2 C8_SUMMER3 C8_SUMMER4 C8_SUMMER5 C8_SUMMER6 C9_SUMMER1 C9_SUMMER2 C9_SUMMER3 C9_SUMMER4 C9_SUMMER5 C9_SUMMER6 C10 C11 CBi_AMP1 CBi_AMP2 CBi_AMP3 CBi_AMP4 CBi_AMP5 CBi_AMP6 CBi_AMP7 CBi_AMP8 CBi_AMP9 CBi_AMP10 CBi_AMP11 CBi_AMP12 CBi_AMP13 CBi_AMP14 CBi_AMP15 CBi_AMP16 CBi_AMP17 CBi_AMP18 CBi_AMP19 CBi_AMP20 CBi_AMP21 CBi_AMP22 CBi_AMP23 CBi_AMP24 CBi_AMP25 CBi_AMP26 CBi_AMP27 CBi_AMP28 CBi_AMP29 CBi_AMP30 CBi_SUMMER1 CBi_SUMMER2 CBi_SUMMER3 CBi_SUMMER4 CBi_SUMMER5 CBi_SUMMER6 CG_SUMMER1 CG_SUMMER2 CG_SUMMER3 CG_SUMMER4 CG_SUMMER5 CG_SUMMER6: "Capacitor"
D1: library part "D Zener", "Zener Diode"
M1_SUMMER1 M1_SUMMER2 M1_SUMMER3 M1_SUMMER4 M1_SUMMER5 M1_SUMMER6: "N-Channel MOSFET"
Q0_AMP1 Q0_AMP2 Q0_AMP3 Q0_AMP4 Q0_AMP5 Q0_AMP6 Q0_AMP7 Q0_AMP8 Q0_AMP9 Q0_AMP10 Q0_AMP11 Q0_AMP12 Q0_AMP13 Q0_AMP14 Q0_AMP15 Q0_AMP16 Q0_AMP17 Q0_AMP18 Q0_AMP19 Q0_AMP20 Q0_AMP21 Q0_AMP22 Q0_AMP23 Q0_AMP24 Q0_AMP25 Q0_AMP26 Q0_AMP27 Q0_AMP28 Q0_AMP29 Q0_AMP30 Q1_AMP1 Q1_AMP2 Q1_AMP3 Q1_AMP4 Q1_AMP5 Q1_AMP6 Q1_AMP7 Q1_AMP8 Q1_AMP9 Q1_AMP10 Q1_AMP11 Q1_AMP12 Q1_AMP13 Q1_AMP14 Q1_AMP15 Q1_AMP16 Q1_AMP17 Q1_AMP18 Q1_AMP19 Q1_AMP20 Q1_AMP21 Q1_AMP22 Q1_AMP23 Q1_AMP24 Q1_AMP25 Q1_AMP26 Q1_AMP27 Q1_AMP28 Q1_AMP29 Q1_AMP30 Q4_SUMMER1 Q4_SUMMER2 Q4_SUMMER3 Q4_SUMMER4 Q4_SUMMER5 Q4_SUMMER6 Q5_SUMMER1 Q5_SUMMER2 Q5_SUMMER3 Q5_SUMMER4 Q5_SUMMER5 Q5_SUMMER6 Q8_SUMMER1 Q8_SUMMER2 Q8_SUMMER3 Q8_SUMMER4 Q8_SUMMER5 Q8_SUMMER6: library part BFR92A, "NPN 5 GHz Wideband Transistor"
Q2_AMP1 Q2_AMP2 Q2_AMP3 Q2_AMP4 Q2_AMP5 Q2_AMP6 Q2_AMP7 Q2_AMP8 Q2_AMP9 Q2_AMP10 Q2_AMP11 Q2_AMP12 Q2_AMP13 Q2_AMP14 Q2_AMP15 Q2_AMP16 Q2_AMP17 Q2_AMP18 Q2_AMP19 Q2_AMP20 Q2_AMP21 Q2_AMP22 Q2_AMP23 Q2_AMP24 Q2_AMP25 Q2_AMP26 Q2_AMP27 Q2_AMP28 Q2_AMP29 Q2_AMP30 Q3_AMP1 Q3_AMP2 Q3_AMP3 Q3_AMP4 Q3_AMP5 Q3_AMP6 Q3_AMP7 Q3_AMP8 Q3_AMP9 Q3_AMP10 Q3_AMP11 Q3_AMP12 Q3_AMP13 Q3_AMP14 Q3_AMP15 Q3_AMP16 Q3_AMP17 Q3_AMP18 Q3_AMP19 Q3_AMP20 Q3_AMP21 Q3_AMP22 Q3_AMP23 Q3_AMP24 Q3_AMP25 Q3_AMP26 Q3_AMP27 Q3_AMP28 Q3_AMP29 Q3_AMP30 Q6_SUMMER1 Q6_SUMMER2 Q6_SUMMER3 Q6_SUMMER4 Q6_SUMMER5 Q6_SUMMER6 Q7_SUMMER1 Q7_SUMMER2 Q7_SUMMER3 Q7_SUMMER4 Q7_SUMMER5 Q7_SUMMER6: library part PNP, "PNP Bipolar Transistor"
R1_AMP1 R1_AMP2 R1_AMP3 R1_AMP4 R1_AMP5 R1_AMP6 R1_AMP7 R1_AMP8 R1_AMP9 R1_AMP10 R1_AMP11 R1_AMP12 R1_AMP13 R1_AMP14 R1_AMP15 R1_AMP16 R1_AMP17 R1_AMP18 R1_AMP19 R1_AMP20 R1_AMP21 R1_AMP22 R1_AMP23 R1_AMP24 R1_AMP25 R1_AMP26 R1_AMP27 R1_AMP28 R1_AMP29 R1_AMP30 R2_AMP1 R2_AMP2 R2_AMP3 R2_AMP4 R2_AMP5 R2_AMP6 R2_AMP7 R2_AMP8 R2_AMP9 R2_AMP10 R2_AMP11 R2_AMP12 R2_AMP13 R2_AMP14 R2_AMP15 R2_AMP16 R2_AMP17 R2_AMP18 R2_AMP19 R2_AMP20 R2_AMP21 R2_AMP22 R2_AMP23 R2_AMP24 R2_AMP25 R2_AMP26 R2_AMP27 R2_AMP28 R2_AMP29 R2_AMP30 R3_AMP1 R3_AMP2 R3_AMP3 R3_AMP4 R3_AMP5 R3_AMP6 R3_AMP7 R3_AMP8 R3_AMP9 R3_AMP10 R3_AMP11 R3_AMP12 R3_AMP13 R3_AMP14 R3_AMP15 R3_AMP16 R3_AMP17 R3_AMP18 R3_AMP19 R3_AMP20 R3_AMP21 R3_AMP22 R3_AMP23 R3_AMP24 R3_AMP25 R3_AMP26 R3_AMP27 R3_AMP28 R3_AMP29 R3_AMP30 R4_AMP1 R4_AMP2 R4_AMP3 R4_AMP4 R4_AMP5 R4_AMP6 R4_AMP7 R4_AMP8 R4_AMP9 R4_AMP10 R4_AMP11 R4_AMP12 R4_AMP13 R4_AMP14 R4_AMP15 R4_AMP16 R4_AMP17 R4_AMP18 R4_AMP19 R4_AMP20 R4_AMP21 R4_AMP22 R4_AMP23 R4_AMP24 R4_AMP25 R4_AMP26 R4_AMP27 R4_AMP28 R4_AMP29 R4_AMP30 R5_AMP1 R5_AMP2 R5_AMP3 R5_AMP4 R5_AMP5 R5_AMP6 R5_AMP7 R5_AMP8 R5_AMP9 R5_AMP10 R5_AMP11 R5_AMP12 R5_AMP13 R5_AMP14 R5_AMP15 R5_AMP16 R5_AMP17 R5_AMP18 R5_AMP19 R5_AMP20 R5_AMP21 R5_AMP22 R5_AMP23 R5_AMP24 R5_AMP25 R5_AMP26 R5_AMP27 R5_AMP28 R5_AMP29 R5_AMP30 R6_AMP1 R6_AMP2 R6_AMP3 R6_AMP4 R6_AMP5 R6_AMP6 R6_AMP7 R6_AMP8 R6_AMP9 R6_AMP10 R6_AMP11 R6_AMP12 R6_AMP13 R6_AMP14 R6_AMP15 R6_AMP16 R6_AMP17 R6_AMP18 R6_AMP19 R6_AMP20 R6_AMP21 R6_AMP22 R6_AMP23 R6_AMP24 R6_AMP25 R6_AMP26 R6_AMP27 R6_AMP28 R6_AMP29 R6_AMP30 R7_AMP1 R7_AMP2 R7_AMP3 R7_AMP4 R7_AMP5 R7_AMP6 R7_AMP7 R7_AMP8 R7_AMP9 R7_AMP10 R7_AMP11 R7_AMP12 R7_AMP13 R7_AMP14 R7_AMP15 R7_AMP16 R7_AMP17 R7_AMP18 R7_AMP19 R7_AMP20 R7_AMP21 R7_AMP22 R7_AMP23 R7_AMP24 R7_AMP25 R7_AMP26 R7_AMP27 R7_AMP28 R7_AMP29 R7_AMP30 R8_AMP1 R8_AMP2 R8_AMP3 R8_AMP4 R8_AMP5 R8_AMP6 R8_AMP7 R8_AMP8 R8_AMP9 R8_AMP10 R8_AMP11 R8_AMP12 R8_AMP13 R8_AMP14 R8_AMP15 R8_AMP16 R8_AMP17 R8_AMP18 R8_AMP19 R8_AMP20 R8_AMP21 R8_AMP22 R8_AMP23 R8_AMP24 R8_AMP25 R8_AMP26 R8_AMP27 R8_AMP28 R8_AMP29 R8_AMP30 R9_SUMMER1 R9_SUMMER2 R9_SUMMER3 R9_SUMMER4 R9_SUMMER5 R9_SUMMER6 R10_SUMMER1 R10_SUMMER2 R10_SUMMER3 R10_SUMMER4 R10_SUMMER5 R10_SUMMER6 R11_SUMMER1 R11_SUMMER2 R11_SUMMER3 R11_SUMMER4 R11_SUMMER5 R11_SUMMER6 R12_SUMMER1 R12_SUMMER2 R12_SUMMER3 R12_SUMMER4 R12_SUMMER5 R12_SUMMER6 R13_SUMMER1 R13_SUMMER2 R13_SUMMER3 R13_SUMMER4 R13_SUMMER5 R13_SUMMER6 R14_SUMMER1 R14_SUMMER2 R14_SUMMER3 R14_SUMMER4 R14_SUMMER5 R14_SUMMER6 R15_SUMMER1 R15_SUMMER2 R15_SUMMER3 R15_SUMMER4 R15_SUMMER5 R15_SUMMER6 R16_SUMMER1 R16_SUMMER2 R16_SUMMER3 R16_SUMMER4 R16_SUMMER5 R16_SUMMER6 R17_SUMMER1 R17_SUMMER2 R17_SUMMER3 R17_SUMMER4 R17_SUMMER5 R17_SUMMER6 R18_AMP1 R18_AMP2 R18_AMP3 R18_AMP4 R18_AMP5 R18_AMP6 R18_AMP7 R18_AMP8 R18_AMP9 R18_AMP10 R18_AMP11 R18_AMP12 R18_AMP13 R18_AMP14 R18_AMP15 R18_AMP16 R18_AMP17 R18_AMP18 R18_AMP19 R18_AMP20 R18_AMP21 R18_AMP22 R18_AMP23 R18_AMP24 R18_AMP25 R18_AMP26 R18_AMP27 R18_AMP28 R18_AMP29 R18_AMP30 R19_AMP1 R19_AMP2 R19_AMP3 R19_AMP4 R19_AMP5 R19_AMP6 R19_AMP7 R19_AMP8 R19_AMP9 R19_AMP10 R19_AMP11 R19_AMP12 R19_AMP13 R19_AMP14 R19_AMP15 R19_AMP16 R19_AMP17 R19_AMP18 R19_AMP19 R19_AMP20 R19_AMP21 R19_AMP22 R19_AMP23 R19_AMP24 R19_AMP25 R19_AMP26 R19_AMP27 R19_AMP28 R19_AMP29 R19_AMP30 R20_AMP1 R20_AMP2 R20_AMP3 R20_AMP4 R20_AMP5 R20_AMP6 R20_AMP7 R20_AMP8 R20_AMP9 R20_AMP10 R20_AMP11 R20_AMP12 R20_AMP13 R20_AMP14 R20_AMP15 R20_AMP16 R20_AMP17 R20_AMP18 R20_AMP19 R20_AMP20 R20_AMP21 R20_AMP22 R20_AMP23 R20_AMP24 R20_AMP25 R20_AMP26 R20_AMP27 R20_AMP28 R20_AMP29 R20_AMP30 R21 R22 R23 R24 R25 R26 R27 RBi_AMP1 RBi_AMP2 RBi_AMP3 RBi_AMP4 RBi_AMP5 RBi_AMP6 RBi_AMP7 RBi_AMP8 RBi_AMP9 RBi_AMP10 RBi_AMP11 RBi_AMP12 RBi_AMP13 RBi_AMP14 RBi_AMP15 RBi_AMP16 RBi_AMP17 RBi_AMP18 RBi_AMP19 RBi_AMP20 RBi_AMP21 RBi_AMP22 RBi_AMP23 RBi_AMP24 RBi_AMP25 RBi_AMP26 RBi_AMP27 RBi_AMP28 RBi_AMP29 RBi_AMP30 RBi_SUMMER1 RBi_SUMMER2 RBi_SUMMER3 RBi_SUMMER4 RBi_SUMMER5 RBi_SUMMER6 RC_SUMMER1 RC_SUMMER2 RC_SUMMER3 RC_SUMMER4 RC_SUMMER5 RC_SUMMER6 RD_SUMMER1 RD_SUMMER2 RD_SUMMER3 RD_SUMMER4 RD_SUMMER5 RD_SUMMER6 RG_SUMMER1 RG_SUMMER2 RG_SUMMER3 RG_SUMMER4 RG_SUMMER5 RG_SUMMER6: "Resistor"
RT1: "Thermistor"
SIPM_AMP1 SIPM_AMP2 SIPM_AMP3 SIPM_AMP4 SIPM_AMP5 SIPM_AMP6 SIPM_AMP7 SIPM_AMP8 SIPM_AMP9 SIPM_AMP10 SIPM_AMP11 SIPM_AMP12 SIPM_AMP13 SIPM_AMP14 SIPM_AMP15 SIPM_AMP16 SIPM_AMP17 SIPM_AMP18 SIPM_AMP19 SIPM_AMP20 SIPM_AMP21 SIPM_AMP22 SIPM_AMP23 SIPM_AMP24 SIPM_AMP25 SIPM_AMP26 SIPM_AMP27 SIPM_AMP28 SIPM_AMP29 SIPM_AMP30: "Photosensitive Diode"
VR1 VR2: "Voltage Regulator"

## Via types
v1: diameter 50, hole 28, Top Layer to Bottom Layer, 433 vias
v2: diameter 50, hole 28, Top Layer to Bottom Layer, tented top, 31 vias

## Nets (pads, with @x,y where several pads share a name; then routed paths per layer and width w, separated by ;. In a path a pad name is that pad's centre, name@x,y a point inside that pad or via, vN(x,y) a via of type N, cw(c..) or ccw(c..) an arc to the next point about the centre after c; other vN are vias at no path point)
+5V: P1.A3 R25.1 R26.1 | length 1519.3
  Top Layer w7: R26.1@1439,3310.78 1439,3307.7 1478.3,3347 v1(1523,3347) ; v1(1683.4,3507.4) R25.1@1745,3507.4
  Bottom Layer w15: v1(1523,3347) v1(1683.4,3507.4) 2054.6,3507.4 ; 2054.6,3504.4 2194,3365 2314,3365 2432,3483 2604.36,3483 P1.A3@2675,3412.36
+5V_2: P1.B32 RT1.2 | length 854.9
  Top Layer w7: P1.B32@5575,3312.36 6063.64,3312.36 6063.64,3310.36 6176,3198 6176,3117 6116,3057 RT1.2@6116,3017.53
BASE1: C10.2 P1.A31 R21.1 R25.2 RBi_SUMMER1.1 RBi_SUMMER2.1 RBi_SUMMER3.1 RBi_SUMMER4.1 RBi_SUMMER5.1 RBi_SUMMER6.1 VR1.3 | length 4850.1
  Top Layer w7: v1(1517,2553) 1550,2520 RBi_SUMMER1.1@1569.22,2520 ; R21.1@1533.15,3500 1592,3500 1677.52,3414.48 v1@1770.52,3414.48 ; R25.2@1744,3478.22 1744,3441 1793.37,3391.63 1793.37,3213.81 1784.56,3205 C10.2@1768.78,3205 ; v1@1768.94,3416.06 2114.94,3416.06 2166,3365 2314,3365 2458,3509 5450,3509 5475,3484 P1.A31@5475,3412.36 ; v1(2432,2553) 2465,2520 RBi_SUMMER2.1@2484.22,2520 ; v1(3340,2553) 3373,2520 RBi_SUMMER3.1@3392.22,2520 ; v1(4251,2553) 4284,2520 RBi_SUMMER4.1@4303.22,2520 ; v1(5164,2553.1) 5197,2520.1 RBi_SUMMER5.1@5216.22,2520.1 ; v1(6075,2553.57) 6108,2520.57 RBi_SUMMER6.1@6127.22,2520.57
  other v1: 1769.94,3415.06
